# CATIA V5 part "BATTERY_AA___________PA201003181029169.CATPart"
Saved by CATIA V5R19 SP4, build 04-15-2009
Part number: BATTERY_AA___________PA201003181029169
Bounding box of the stored display mesh (mm): x -7 to 7, y -7 to 7, z 0 to 51
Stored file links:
  E:\CadInnWork\1\BATTERY_AA___________PA201003181029169.CATPart
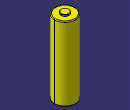
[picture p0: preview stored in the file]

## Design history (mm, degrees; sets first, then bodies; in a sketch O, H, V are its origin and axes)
Parameters
  Update = false
  PDM_version = "A"
  PDM_iteration = 1
  PDM_owner = "moren                    "
  PDM_comment = ""
  PDM_partnumber = "PA002170EA6A57201003181029160009"
Body1 (main body)
  Sketch1 on xy-plane, origin (0, 0, 0), H (1, 0, 0), V (0, 1, 0)
    circle A1 centre (0, 0) radius 7
    radius A1 = 7
  Pad1: profile Sketch1, direction (0, 0, 1), length 50
  Sketch2 on end face of Pad1, origin (0, 0, 50), H (1, 0, 0), V (0, 1, 0)
    circle A1 centre (0, 0) radius 2.75
    radius A1 = 2.75
  Pad2: profile Sketch2, direction (0, 0, 1), length 1
  Fillet1: radius 0.5, on edge [face of Pad1 from Sketch1.A1 | end face of Pad1]; edge [start face of Pad1 | face of Pad1 from Sketch1.A1]
  Fillet2: radius 0.2, on edge [face of Pad2 from Sketch2.A1 | end face of Pad2]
